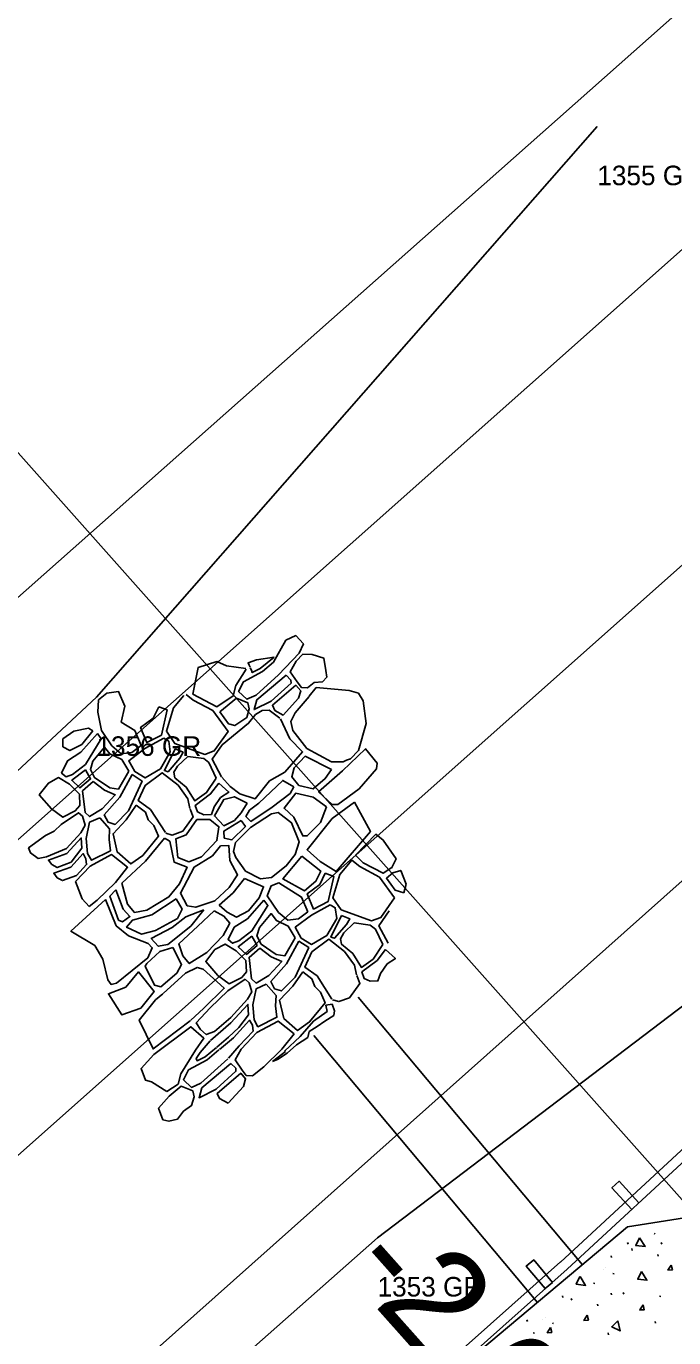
# Model space of a CAD drawing. Extents: x 49683 to 58852, y 49525 to 54803.
# Drawn here: x 53904.9 to 53938, y 51882.6 to 51949.6 of the extents above; entities that cross this region are included whole.
import ezdxf

# ---------------------------------------------------------------- set-up
doc = ezdxf.new("R2010")
doc.units = 0
for name, color, linetype in [('Level 1', 7, 'Continuous'), ('Level 11', 7, 'Continuous'), ('Level 16', 7, 'Continuous'), ('Level 27', 7, 'Continuous'), ('Level 3', 7, 'Continuous'), ('Level 50', 7, 'Continuous'), ('Level 57', 7, 'Continuous'), ('Level 63', 7, 'Continuous'), ('Level 7', 7, 'Continuous'), ('Level 8', 7, 'Continuous')]:
    doc.layers.add(name, color=color, linetype=linetype)

msp = doc.modelspace()

# ---------------------------------------------------------------- linework, layer by layer
at = {"layer": 'Level 1'}
msp.add_line((52544.807, 50683.302), (55534.583, 53340.862), dxfattribs=at)
at = {"layer": 'Level 11'}
msp.add_line((53894.91, 51911.927), (54324.203, 52292.615), dxfattribs=at)
at = {"layer": 'Level 16'}
for p, q in [((53919.586, 51898.734), (53920.281, 51899.24)), ((53920.612, 51899.034), (53920.154, 51898.734)), ((53920.202, 51899.556), (53920.533, 51899.603)), ((53920.281, 51899.24), (53920.202, 51899.556)), ((53920.533, 51899.603), (53920.66, 51899.272)), ((53920.66, 51899.272), (53920.612, 51899.034)), ((53918.891, 51897.96), (53919.586, 51898.734)), ((53919.76, 51898.466), (53919.365, 51898.213)), ((53920.154, 51898.734), (53919.76, 51898.466)), ((53918.102, 51897.201), (53918.891, 51897.96)), ((53919.286, 51897.897), (53918.718, 51897.533)), ((53919.365, 51898.213), (53919.286, 51897.897)), ((53917.486, 51896.68), (53918.149, 51897.185)), ((53918.228, 51897.106), (53917.739, 51896.774)), ((53918.149, 51897.185), (53918.102, 51897.201)), ((53918.718, 51897.533), (53918.228, 51897.106)), ((53917.739, 51896.774), (53917.486, 51896.68))]:
    msp.add_line(p, q, dxfattribs=at)
for points in [[(53917.54, 51917.09), (53918.174, 51918.207), (53918.683, 51918.453), (53919.065, 51918.029), (53918.846, 51917.556), (53917.785, 51916.441)], [(53913.408, 51915.456), (53913.683, 51916.814), (53914.645, 51917.123), (53915.139, 51916.896), (53916.114, 51916.77)], [(53916.34, 51916.835), (53916.291, 51916.931), (53916.234, 51917.05), (53916.662, 51917.206), (53917.566, 51917.34)], [(53916.34, 51916.805), (53916.403, 51916.678), (53916.451, 51916.555), (53916.856, 51916.764), (53917.566, 51917.34)], [(53917.526, 51917.314), (53917.457, 51917.254)], [(53919.03, 51917.497), (53918.695, 51917.144), (53918.393, 51916.596), (53918.75, 51916.083), (53918.962, 51915.804), (53919.274, 51915.782), (53919.611, 51916.054)], [(53919.03, 51917.497), (53919.516, 51917.475), (53920.113, 51917.29), (53920.212, 51916.672), (53920.253, 51916.324), (53920.043, 51916.091), (53919.611, 51916.054)], [(53913.408, 51915.456), (53914.636, 51914.813), (53915.482, 51915.366), (53915.618, 51915.893), (53916.133, 51916.729)], [(53917.54, 51917.09), (53916.966, 51916.605), (53916.01, 51916.089), (53915.752, 51915.587), (53916.168, 51915.195), (53916.646, 51915.404), (53917.785, 51916.441)], [(53919.366, 51915.346), (53919.722, 51915.792)], [(53921.27, 51912.075), (53921.474, 51912.15), (53921.886, 51912.57), (53922.275, 51913.952), (53922.116, 51915.107), (53921.874, 51915.506), (53921.397, 51915.649), (53919.722, 51915.792)], [(53908.741, 51913.602), (53908.551, 51914.54), (53908.596, 51915.164), (53909.026, 51915.498), (53909.615, 51915.591), (53909.936, 51914.833), (53909.757, 51914.03)], [(53912.952, 51915.391), (53912.419, 51914.75), (53912.062, 51913.561), (53912.49, 51912.936), (53914.033, 51912.375), (53914.511, 51912.559), (53915.211, 51913.552), (53914.44, 51914.617), (53913.436, 51915.155), (53913.065, 51915.439)], [(53921.27, 51912.075), (53921.091, 51911.99), (53920.503, 51911.989), (53919.244, 51912.68), (53918.532, 51913.603), (53918.417, 51914.055), (53918.648, 51914.496), (53919.351, 51915.331)], [(53917.859, 51914.22), (53917.319, 51914.633), (53916.964, 51914.62), (53916.608, 51914.411), (53916.265, 51913.97), (53914.916, 51912.866), (53914.4, 51912.13), (53914.877, 51911.235)], [(53908.741, 51913.602), (53909.28, 51912.81), (53909.757, 51912.406), (53910.296, 51912.481), (53910.775, 51912.836), (53910.457, 51913.596), (53909.757, 51914.03)], [(53917.885, 51914.194), (53918.374, 51913.173), (53919.024, 51912.502), (53918.12, 51911.472), (53917.332, 51911.02), (53916.607, 51910.106), (53915.809, 51910.357), (53915.327, 51910.734), (53914.903, 51911.208)], [(53906.774, 51912.758), (53906.774, 51913.164), (53907.338, 51913.559), (53908.084, 51913.711)], [(53906.774, 51912.758), (53907.133, 51912.571), (53907.745, 51912.888), (53908.311, 51913.585)], [(53908.084, 51913.711), (53908.311, 51913.585)], [(53921.068, 51911.536), (53922.235, 51912.669), (53922.825, 51911.925), (53922.8, 51911.632), (53921.906, 51910.623)], [(53905.561, 51910.304), (53906.186, 51909.59), (53906.766, 51909.166), (53907.404, 51909.491), (53907.639, 51909.77), (53907.617, 51910.351), (53907.115, 51910.854), (53906.556, 51911.188), (53906.031, 51910.908), (53905.561, 51910.304)], [(53913.26, 51909.612), (53913.161, 51910.107), (53912.659, 51910.805), (53911.851, 51911.441), (53910.981, 51910.791), (53910.624, 51910.018), (53911.249, 51909.566), (53912.011, 51908.376)], [(53921.068, 51911.536), (53919.84, 51910.466), (53920.532, 51909.816), (53920.826, 51909.817), (53921.906, 51910.623)], [(53906.956, 51907.559), (53907.693, 51908.374), (53907.917, 51908.754), (53907.772, 51909.212), (53907.571, 51909.391), (53906.688, 51908.797), (53906.325, 51908.453)], [(53913.275, 51909.585), (53913.437, 51909.179), (53912.899, 51908.451), (53912.361, 51908.25), (53912.038, 51908.347)], [(53906.956, 51907.559), (53905.942, 51907.138), (53905.509, 51907.054), (53905.125, 51907.343), (53905.024, 51907.592), (53905.879, 51908.226), (53906.325, 51908.453)], [(53906.969, 51907.303), (53907.715, 51908.106), (53907.748, 51907.581), (53907.202, 51906.866)], [(53921.727, 51907.232), (53922.769, 51908.295), (53923.148, 51907.993), (53923.799, 51907.032), (53923.565, 51906.565)], [(53907.202, 51906.866), (53906.482, 51906.594), (53906.216, 51906.74), (53906.035, 51906.973), (53906.969, 51907.303)], [(53907.461, 51906.19), (53907.982, 51906.743), (53907.948, 51907.045), (53907.803, 51907.302), (53907.181, 51906.611)], [(53908.119, 51904.593), (53908.527, 51904.923), (53909.455, 51905.829), (53910.082, 51906.611), (53909.256, 51907.258), (53908.171, 51906.665), (53907.424, 51905.876)], [(53921.727, 51907.232), (53922.119, 51906.84), (53923.148, 51906.302), (53923.585, 51906.587)], [(53907.461, 51906.19), (53906.751, 51905.922), (53906.485, 51906.069), (53906.304, 51906.301), (53907.181, 51906.611)], [(53923.632, 51906.314), (53924.034, 51906.445), (53924.315, 51905.745), (53924.192, 51905.296)], [(53907.424, 51905.876), (53907.759, 51904.998), (53908.119, 51904.593)], [(53923.632, 51906.314), (53923.307, 51906.045), (53923.747, 51905.433), (53924.192, 51905.296)], [(53908.956, 51904.957), (53907.185, 51903.337), (53908.405, 51902.608), (53908.821, 51901.915), (53909.062, 51900.855), (53909.238, 51900.615), (53909.513, 51900.686)], [(53908.956, 51904.957), (53909.5, 51903.62), (53910.121, 51903.105), (53911.133, 51902.705), (53911.343, 51902.495), (53911.121, 51901.978), (53909.513, 51900.686)], [(53923.446, 51904.381), (53922.912, 51903.618), (53923.389, 51902.723)], [(53921.772, 51901.1), (53921.672, 51901.595), (53921.171, 51902.293), (53920.363, 51902.929), (53919.492, 51902.279), (53919.136, 51901.507), (53919.76, 51901.054), (53920.523, 51899.864)], [(53910.76, 51899.398), (53911.431, 51900.253), (53910.634, 51901.26), (53909.985, 51900.478)], [(53913.289, 51898.766), (53913.981, 51899.402), (53915.021, 51900.42), (53913.949, 51901.402), (53913.637, 51901.491), (53913.033, 51901.2), (53911.894, 51900.16)], [(53921.787, 51901.073), (53921.949, 51900.667), (53921.411, 51899.94), (53920.873, 51899.739), (53920.549, 51899.835)], [(53910.76, 51899.398), (53909.792, 51899.062), (53909.099, 51900.143), (53909.985, 51900.478)], [(53911.877, 51900.143), (53911.506, 51899.824), (53910.671, 51898.794), (53911.38, 51897.325), (53913.271, 51898.749)], [(53914.32, 51897.753), (53915.354, 51898.655), (53916.226, 51899.594), (53916.259, 51899.069), (53915.756, 51898.41), (53915.23, 51897.929), (53914.64, 51897.414)], [(53912.09, 51895.15), (53912.665, 51895.525), (53912.8, 51896.052), (53913.549, 51897.266), (53913.978, 51897.867), (53913.317, 51898.454), (53911.422, 51897.041)], [(53915.231, 51896.842), (53915.777, 51897.471), (53916.493, 51898.232), (53916.46, 51898.533), (53916.315, 51898.79), (53915.498, 51897.884), (53914.775, 51897.298)], [(53914.295, 51897.728), (53913.781, 51897.131), (53913.585, 51896.837), (53913.634, 51896.715), (53914.039, 51896.923), (53914.622, 51897.396)], [(53912.09, 51895.15), (53911.299, 51895.644), (53910.995, 51895.716), (53910.773, 51896.313), (53911.422, 51897.041)], [(53914.75, 51897.273), (53914.149, 51896.764), (53913.192, 51896.249), (53912.935, 51895.746), (53913.351, 51895.354), (53913.829, 51895.563), (53915.206, 51896.818)], [(53915.212, 51894.548), (53915.997, 51895.406), (53916.108, 51895.786), (53915.863, 51896.08), (53914.661, 51895.05), (53914.783, 51894.78), (53915.212, 51894.548)], [(53912.933, 51894.14), (53913.35, 51894.423), (53913.473, 51894.864), (53913.412, 51895.171), (53912.824, 51895.415), (53912.201, 51894.9)], [(53912.933, 51894.14), (53912.635, 51893.735), (53912.189, 51893.628), (53911.885, 51893.701), (53911.663, 51894.297), (53912.201, 51894.9)]]:
    msp.add_lwpolyline(points, dxfattribs=at)
for points in [[(53918.179, 51916.422), (53916.683, 51915.171), (53916.547, 51914.669), (53917.418, 51915.098), (53918.436, 51916.018), (53918.424, 51916.178)], [(53918.681, 51915.921), (53917.479, 51914.89), (53917.601, 51914.621), (53918.03, 51914.388), (53918.815, 51915.247), (53918.925, 51915.627)], [(53914.795, 51914.556), (53915.236, 51913.944), (53915.554, 51913.847), (53916.167, 51914.264), (53916.29, 51914.705), (53916.229, 51915.011), (53915.641, 51915.256)], [(53911.671, 51914.81), (53912.1, 51914.651), (53911.817, 51913.364), (53911.069, 51912.984), (53910.739, 51913.755), (53911.389, 51914.234)], [(53908.537, 51913.436), (53907.698, 51912.485), (53907.016, 51912.049), (53906.702, 51911.423), (53906.936, 51911.233), (53907.261, 51911.357), (53907.92, 51911.86), (53908.737, 51913.168)], [(53911.927, 51913.205), (53910.958, 51912.677), (53910.137, 51912.052), (53910.442, 51911.501), (53910.969, 51911.17), (53911.753, 51911.637), (53912.257, 51912.507), (53912.184, 51913.046)], [(53910.136, 51911.512), (53909.781, 51912.112), (53909.169, 51912.406), (53908.9, 51912.749), (53908.311, 51912.037), (53908.176, 51911.608), (53908.396, 51911.192), (53909.167, 51910.666), (53909.608, 51910.593)], [(53912.502, 51912.655), (53911.962, 51911.551), (53912.145, 51911.49), (53912.746, 51912.189), (53912.918, 51912.484)], [(53914.608, 51911.162), (53914.117, 51910.427), (53913.516, 51909.997), (53913.076, 51910.707), (53912.5, 51911.184), (53912.439, 51911.466), (53912.623, 51911.773), (53913.151, 51912.276), (53913.972, 51912.166), (53914.229, 51911.958)], [(53920.503, 51911.611), (53919.16, 51912.281), (53918.592, 51911.693), (53918.466, 51911.231), (53918.833, 51910.78), (53919.567, 51910.613), (53920.177, 51911.138)], [(53907.92, 51911.592), (53907.227, 51911.055), (53907.64, 51910.664), (53908.188, 51911.123)], [(53910.311, 51911.349), (53909.684, 51910.186), (53908.889, 51909.28), (53909.079, 51908.912), (53909.436, 51908.801), (53910.13, 51909.494), (53910.824, 51911.014)], [(53908.322, 51910.989), (53907.774, 51910.508), (53907.906, 51909.413), (53908.141, 51909.201), (53908.778, 51909.593), (53909.449, 51910.309), (53908.902, 51910.543)], [(53914.75, 51910.912), (53914.319, 51910.355), (53913.541, 51909.766), (53913.656, 51909.441), (53913.971, 51909.294), (53914.359, 51909.305), (53914.496, 51909.694), (53914.833, 51910.177), (53915.253, 51910.451)], [(53918.581, 51910.717), (53918.004, 51911.042), (53916.785, 51909.885), (53916.312, 51909.518), (53916.123, 51909.202), (53916.374, 51908.951), (53917.467, 51909.687), (53918.391, 51910.381)], [(53920.249, 51909.7), (53919.567, 51910.193), (53918.675, 51910.391), (53918.076, 51909.624), (53918.579, 51909.163), (53919.029, 51908.208), (53919.26, 51908.209), (53919.943, 51908.892)], [(53910.521, 51909.774), (53910.006, 51909.036), (53909.335, 51908.32), (53909.546, 51907.393), (53910.25, 51906.779), (53910.865, 51907.216), (53911.659, 51908.189), (53911.425, 51908.736), (53911.135, 51909.026), (53910.99, 51909.417)], [(53916.197, 51909.885), (53915.536, 51910.209), (53915.001, 51910.072), (53914.517, 51909.232), (53914.999, 51908.729), (53915.535, 51908.992), (53915.881, 51909.381)], [(53921.682, 51909.927), (53920.541, 51909.105), (53919.253, 51907.498), (53919.926, 51906.899), (53920.746, 51906.397), (53922.489, 51908.433)], [(53908.655, 51909.135), (53908.14, 51908.911), (53907.961, 51908.084), (53908.038, 51907.313), (53908.228, 51906.967), (53909.2, 51907.448), (53909.134, 51908.029), (53909.157, 51908.566)], [(53913.616, 51909.042), (53913.078, 51908.272), (53912.551, 51908.061), (53912.655, 51907.112), (53913.213, 51906.892), (53913.857, 51907.135), (53914.648, 51907.968), (53914.744, 51908.675), (53914.28, 51909.053)], [(53917.782, 51909.414), (53917.435, 51909.34), (53916.364, 51908.646), (53915.586, 51907.869), (53915.491, 51907.417), (53915.616, 51907.102), (53916.099, 51906.41), (53916.864, 51906.023), (53917.431, 51906.086), (53918.188, 51906.675), (53918.64, 51907.253), (53918.84, 51907.914), (53918.463, 51908.88)], [(53915.881, 51909.003), (53914.999, 51908.456), (53915.019, 51908.099), (53915.408, 51908.005), (53916.101, 51908.698)], [(53911.961, 51908.102), (53912.235, 51907.934), (53912.455, 51906.87), (53913.118, 51906.607), (53912.727, 51905.753), (53912.189, 51905.088), (53911.071, 51904.413), (53910.428, 51904.296), (53910.07, 51904.717), (53909.787, 51905.802), (53911, 51906.91)], [(53914.827, 51907.705), (53914.426, 51907.199), (53913.487, 51906.618), (53912.78, 51905.279), (53913.127, 51904.636), (53913.559, 51904.563), (53914.539, 51904.891), (53915.278, 51905.566), (53915.7, 51906.22), (53915.3, 51906.957), (53915.259, 51907.716)], [(53918.983, 51907.179), (53918.014, 51906.014), (53919.116, 51905.403), (53919.704, 51905.894), (53919.95, 51906.408)], [(53923.722, 51905.041), (53922.951, 51906.106), (53921.947, 51906.644), (53921.531, 51906.962), (53920.93, 51906.238), (53920.573, 51905.049), (53921.001, 51904.425), (53922.545, 51903.863), (53923.023, 51904.047)], [(53916.058, 51906.031), (53915.467, 51905.292), (53914.76, 51904.67), (53915.16, 51904.312), (53915.645, 51904.06), (53916.256, 51904.376), (53916.805, 51905.052), (53917.027, 51905.61)], [(53919.286, 51904.325), (53918.968, 51905.084), (53917.805, 51905.806), (53917.413, 51905.658), (53917.216, 51905.143), (53917.791, 51904.299), (53918.269, 51903.895), (53918.808, 51903.969)], [(53920.183, 51906.299), (53920.611, 51906.14), (53920.328, 51904.853), (53919.58, 51904.472), (53919.25, 51905.244), (53919.9, 51905.722)], [(53909.481, 51905.454), (53909.859, 51904.464), (53910.196, 51904.085), (53909.827, 51903.821), (53909.616, 51903.905), (53909.175, 51905.127)], [(53912.558, 51904.994), (53912.863, 51904.457), (53912.631, 51903.993), (53911.513, 51903.38), (53910.785, 51903.179), (53910.027, 51903.537), (53910.322, 51903.895), (53911.324, 51904.181)], [(53913.969, 51904.427), (53913.063, 51904.067), (53912.356, 51903.529), (53911.291, 51902.969), (53911.649, 51902.569), (53912.134, 51902.654), (53913.315, 51903.604)], [(53914.507, 51904.374), (53915.002, 51904.112), (53915.297, 51903.754), (53914.959, 51903.121), (53914.136, 51902.256), (53913.229, 51901.686), (53912.902, 51902.075), (53912.692, 51902.686), (53913.663, 51903.594)], [(53917.048, 51904.924), (53916.209, 51903.974), (53915.527, 51903.537), (53915.214, 51902.911), (53915.448, 51902.722), (53915.772, 51902.845), (53916.432, 51903.349), (53917.249, 51904.657)], [(53920.438, 51904.694), (53919.47, 51904.166), (53918.648, 51903.54), (53918.954, 51902.989), (53919.48, 51902.659), (53920.265, 51903.125), (53920.768, 51903.996), (53920.695, 51904.535)], [(53918.648, 51903.001), (53918.293, 51903.601), (53917.681, 51903.894), (53917.412, 51904.237), (53916.823, 51903.526), (53916.687, 51903.097), (53916.907, 51902.68), (53917.679, 51902.155), (53918.12, 51902.081)], [(53921.013, 51904.143), (53920.473, 51903.04), (53920.657, 51902.979), (53921.258, 51903.678), (53921.43, 51903.972)], [(53923.119, 51902.651), (53922.628, 51901.915), (53922.027, 51901.486), (53921.587, 51902.196), (53921.012, 51902.673), (53920.951, 51902.955), (53921.135, 51903.261), (53921.662, 51903.764), (53922.483, 51903.655), (53922.74, 51903.447)], [(53916.432, 51903.08), (53915.738, 51902.543), (53916.151, 51902.153), (53916.699, 51902.611)], [(53912.386, 51902.507), (53911.733, 51902.295), (53911.068, 51901.694), (53910.984, 51901.546), (53911.446, 51900.577), (53911.783, 51900.493), (53912.596, 51901.2), (53912.839, 51901.633)], [(53916.15, 51901.259), (53916.128, 51901.84), (53915.626, 51902.342), (53915.068, 51902.677), (53914.543, 51902.397), (53914.073, 51901.793), (53914.697, 51901.079), (53915.278, 51900.655), (53915.915, 51900.979)], [(53916.833, 51902.478), (53916.285, 51901.996), (53916.418, 51900.902), (53916.652, 51900.69), (53917.289, 51901.081), (53917.961, 51901.797), (53917.414, 51902.031)], [(53918.822, 51902.837), (53918.195, 51901.675), (53917.401, 51900.769), (53917.59, 51900.4), (53917.948, 51900.289), (53918.641, 51900.982), (53919.336, 51902.503)], [(53923.261, 51902.4), (53922.83, 51901.843), (53922.053, 51901.255), (53922.168, 51900.929), (53922.482, 51900.783), (53922.871, 51900.794), (53923.008, 51901.182), (53923.344, 51901.666), (53923.764, 51901.939)], [(53919.033, 51901.262), (53918.518, 51900.524), (53917.847, 51899.808), (53918.058, 51898.881), (53918.761, 51898.268), (53919.376, 51898.704), (53920.17, 51899.677), (53919.936, 51900.224), (53919.646, 51900.514), (53919.501, 51900.905)], [(53916.083, 51900.879), (53915.199, 51900.286), (53914.293, 51899.425), (53913.589, 51898.653), (53913.801, 51898.307), (53914.102, 51898.05), (53914.516, 51898.218), (53915.354, 51898.923), (53916.204, 51899.862), (53916.428, 51900.243), (53916.284, 51900.701)], [(53917.166, 51900.623), (53916.652, 51900.399), (53916.472, 51899.572), (53916.55, 51898.801), (53916.739, 51898.455), (53917.712, 51898.937), (53917.645, 51899.518), (53917.668, 51900.054)], [(53918.593, 51898.1), (53917.767, 51898.747), (53916.683, 51898.154), (53915.878, 51897.304), (53915.575, 51896.756), (53915.932, 51896.242), (53916.144, 51895.963), (53916.457, 51895.941), (53917.038, 51896.411), (53917.967, 51897.317)], [(53915.361, 51896.582), (53913.865, 51895.33), (53913.73, 51894.828), (53914.6, 51895.258), (53915.618, 51896.178), (53915.606, 51896.337)]]:
    msp.add_lwpolyline(points, close=True, dxfattribs=at)
at = {"layer": 'Level 27'}
for p, q in [((53932.197, 51886.425), (53968.904, 51920.39)), ((53932.537, 51886.058), (53969.243, 51920.023)), ((53932.205, 51886.431), (53908.848, 51865.67)), ((53932.537, 51886.058), (53909.18, 51865.296))]:
    msp.add_line(p, q, dxfattribs=at)
for points in [[(53936.209, 51889.453), (53935.839, 51889.116), (53934.829, 51890.224), (53935.198, 51890.561)], [(53931.795, 51885.388), (53931.411, 51885.067), (53930.449, 51886.218), (53930.833, 51886.539)]]:
    msp.add_lwpolyline(points, close=True, dxfattribs=at)
at = {"layer": 'Level 3'}
for p, q in [((53883.273, 51889.178), (54069.537, 52054.718)), ((53898.742, 51870.567), (54083.389, 52035.124))]:
    msp.add_line(p, q, dxfattribs=at)
at = {"layer": 'Level 50'}
msp.add_line((53872.475, 51963.789), (54031.921, 51784.41), dxfattribs=at)
at = {"layer": 'Level 7'}
for p, q in [((53934.082, 51944.47), (53908.487, 51915.299)), ((53908.487, 51915.299), (53883.022, 51891.572)), ((53922.854, 51887.665), (53958.852, 51915.059)), ((53902.065, 51869.327), (53922.854, 51887.665))]:
    msp.add_line(p, q, dxfattribs=at)
at = {"layer": 'Level 8'}
for p, q in [((53933.325, 51886.292), (53921.868, 51899.962)), ((53931.026, 51884.365), (53919.596, 51898.002)), ((53935.625, 51888.219), (53953.195, 51891.04)), ((53924.129, 51878.584), (53935.625, 51888.219)), ((53937.045, 51887.867), (53936.981, 51887.886)), ((53935.631, 51887.423), (53935.655, 51887.336)), ((53935.843, 51887.113), (53935.867, 51887.025)), ((53937.348, 51887.426), (53937.372, 51887.338)), ((53934.789, 51886.743), (53934.813, 51886.655)), ((53937.175, 51886.819), (53937.199, 51886.731)), ((53934.374, 51886.047), (53934.374, 51886.047)), ((53934.503, 51886.153), (53934.503, 51886.153)), ((53934.939, 51885.83), (53934.875, 51885.849)), ((53933.956, 51885.326), (53933.892, 51885.346)), ((53932.296, 51884.701), (53932.321, 51884.614)), ((53932.754, 51884.572), (53932.778, 51884.484)), ((53934.086, 51884.278), (53934.11, 51884.19)), ((53934.79, 51884.834), (53934.814, 51884.746)), ((53935.412, 51884.878), (53935.437, 51884.79)), ((53937.327, 51884.668), (53937.263, 51884.688)), ((53931.413, 51883.612), (53931.413, 51883.612)), ((53930.483, 51883.47), (53930.508, 51883.382)), ((53931.285, 51883.506), (53931.285, 51883.506)), ((53931.85, 51883.289), (53931.786, 51883.309)), ((53937.038, 51883.389), (53937.062, 51883.301)), ((53930.867, 51882.786), (53930.803, 51882.805)), ((53934.632, 51882.801), (53934.656, 51882.713))]:
    msp.add_line(p, q, dxfattribs=at)
for points in [[(53936.245, 51887.669), (53936.524, 51887.214), (53936.051, 51887.268), (53936.24, 51887.661)], [(53937.86, 51886.274), (53937.921, 51886.025), (53937.69, 51886.015), (53937.86, 51886.274)], [(53933.202, 51885.692), (53933.481, 51885.237), (53933.008, 51885.291), (53933.197, 51885.684)], [(53936.342, 51885.951), (53936.621, 51885.496), (53936.148, 51885.55), (53936.337, 51885.943)], [(53933.569, 51883.706), (53933.63, 51883.457), (53933.399, 51883.447), (53933.569, 51883.706)], [(53936.424, 51884.237), (53936.485, 51883.988), (53936.254, 51883.978), (53936.424, 51884.237)], [(53931.692, 51883.076), (53931.753, 51882.827), (53931.522, 51882.816), (53931.692, 51883.076)], [(53935.139, 51883.43), (53935.246, 51882.908), (53934.82, 51883.12), (53935.132, 51883.425)]]:
    msp.add_lwpolyline(points, dxfattribs=at)

# ---------------------------------------------------------------- texts
at = {"layer": 'Level 57'}
for s, p in [('1355 GRA', (53934.083, 51941.47)), ('1356 GR', (53908.487, 51912.299)), ('1353 GR', (53922.854, 51884.665))]:
    msp.add_text(s, height=1, dxfattribs=at).set_placement(p)
at = {"layer": 'Level 63'}
msp.add_text('-2.08', height=5.25, rotation=311.63346, dxfattribs=at).set_placement((53921.058, 51886.024))

doc.saveas('drawing.dxf')
